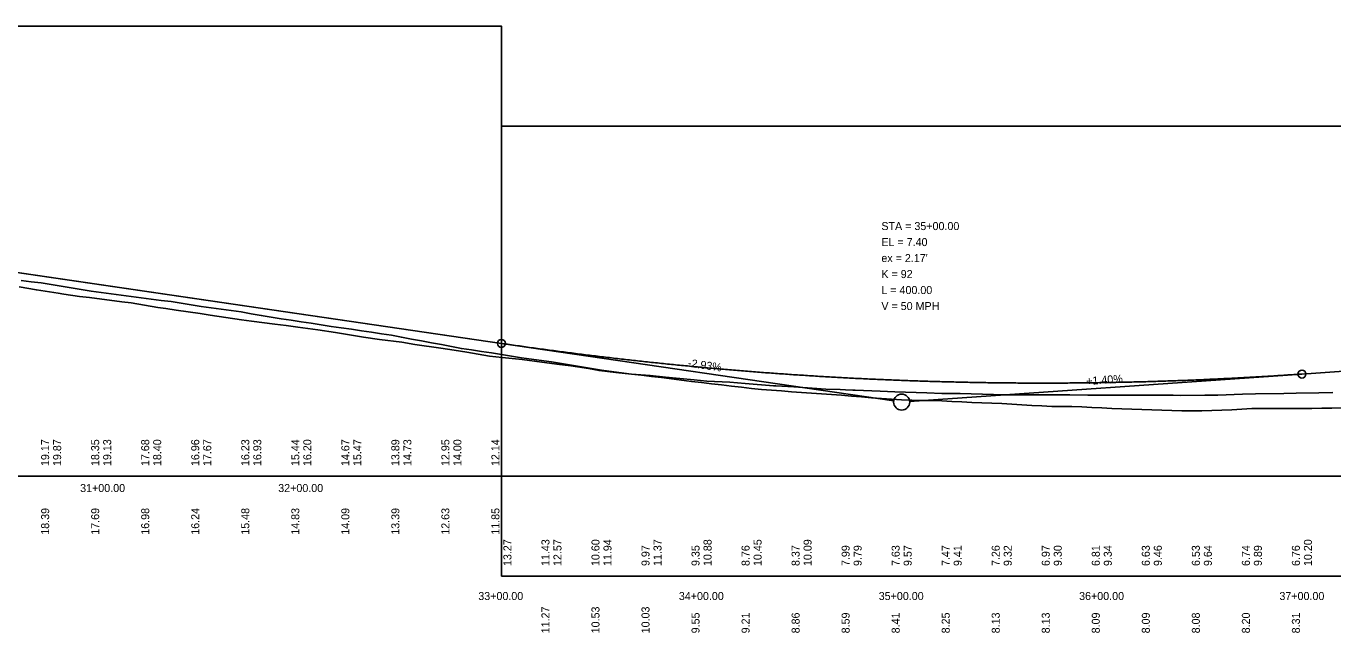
# Model space of a CAD drawing. Extents: x 3880794 to 3915434, y 287517 to 300173.
# Drawn here: x 3883601 to 3884254, y 297646 to 297949 of the extents above; entities that cross this region are included whole.
import ezdxf

# ---------------------------------------------------------------- set-up
doc = ezdxf.new("R2010")
doc.units = 0
for name, color, linetype in [('Level 1', 7, 'Continuous'), ('Level 2', 7, 'Continuous'), ('Level 30', 7, 'Continuous'), ('Level 31', 7, 'Continuous'), ('Level 32', 7, 'Continuous'), ('Level 62', 7, 'Continuous'), ('Level 63', 7, 'Continuous')]:
    doc.layers.add(name, color=color, linetype=linetype)

msp = doc.modelspace()

# ---------------------------------------------------------------- linework, layer by layer
at = {"layer": 'Level 1'}
for p, q in [((3883588.3, 297827.19), (3883838.3, 297790.52)), ((3884238.3, 297775.21), (3884538.3, 297796.23)), ((3883838.3, 297790.52), (3884034.34, 297761.77)), ((3884238.3, 297775.21), (3884042.29, 297761.47))]:
    msp.add_line(p, q, dxfattribs=at)
for points in [[(3883597.27, 297818.81), (3883605.94, 297817.28), (3883608.11, 297816.93), (3883616.77, 297815.59), (3883619.58, 297815.2), (3883627.5, 297814.06), (3883632.4, 297813.44), (3883648.68, 297811.25), (3883653.27, 297810.78), (3883666.53, 297808.52), (3883670.58, 297807.97), (3883675.8, 297807.19), (3883687.69, 297805.5), (3883692.79, 297804.56), (3883708.37, 297802.27), (3883713.41, 297801.58), (3883725, 297800.11), (3883730.7, 297799.51), (3883736.6, 297798.6), (3883746.62, 297797.24), (3883755.31, 297795.95), (3883769.41, 297793.64), (3883777.4, 297792.55), (3883788.55, 297791.08), (3883795.02, 297789.98), (3883808.04, 297788.14), (3883814.74, 297787.15), (3883821.01, 297786.18), (3883832.36, 297784.19), (3883838.61, 297783.4), (3883848.7, 297782.42), (3883858.55, 297781.16), (3883867.33, 297780.02)], [(3883867.33, 297780.02), (3883872.99, 297779.35), (3883881.77, 297777.94), (3883887.06, 297776.97), (3883895.54, 297776.01), (3883903.3, 297775.16), (3883912.6, 297774.39), (3883920.25, 297773.64), (3883934.56, 297772.27), (3883940.92, 297771.69), (3883952.45, 297771.11), (3883960.07, 297770.53), (3883974.32, 297769.31), (3883975.36, 297769.25), (3883984.42, 297768.74), (3884000.42, 297767.69), (3884007.61, 297767.44), (3884010.28, 297767.27), (3884013.95, 297767.13), (3884015.09, 297767.09), (3884027.62, 297766.65), (3884034.83, 297766.36), (3884050.85, 297765.81), (3884058.38, 297765.5), (3884059.22, 297765.48), (3884067.5, 297765.39), (3884084.25, 297764.94), (3884088.11, 297764.84), (3884095.69, 297764.82), (3884105.7, 297764.82), (3884115.48, 297764.82), (3884122.37, 297764.74), (3884131.29, 297764.68), (3884136.3, 297764.65), (3884146.02, 297764.64), (3884152.71, 297764.62), (3884164.32, 297764.63), (3884173.94, 297764.62), (3884177.81, 297764.54), (3884189.81, 297764.62), (3884196.23, 297764.68), (3884208.54, 297765.08), (3884215.17, 297765.22), (3884229.31, 297765.53), (3884235.38, 297765.69), (3884246.77, 297765.83), (3884253.82, 297765.93)]]:
    msp.add_lwpolyline(points, dxfattribs=at)
msp.add_circle((3884038.3, 297761.19), 4, dxfattribs=at)
msp.add_spline([(3883838.3, 297790.52), (3883846.3, 297789.37), (3883854.3, 297788.25), (3883862.3, 297787.16), (3883870.3, 297786.11), (3883878.3, 297785.09), (3883886.3, 297784.11), (3883894.3, 297783.16), (3883902.3, 297782.25), (3883910.3, 297781.37), (3883918.3, 297780.52), (3883926.3, 297779.72), (3883934.3, 297778.94), (3883942.3, 297778.2), (3883950.3, 297777.5), (3883958.3, 297776.83), (3883966.3, 297776.19), (3883974.3, 297775.59), (3883982.3, 297775.02), (3883990.3, 297774.49), (3883998.3, 297773.99), (3884006.3, 297773.53), (3884014.3, 297773.1), (3884022.3, 297772.71), (3884030.3, 297772.35), (3884038.3, 297772.03), (3884046.3, 297771.74), (3884054.3, 297771.48), (3884062.3, 297771.27), (3884070.3, 297771.08), (3884078.3, 297770.93), (3884086.3, 297770.81), (3884094.3, 297770.73), (3884102.3, 297770.69), (3884110.3, 297770.67), (3884118.3, 297770.7), (3884126.3, 297770.76), (3884134.3, 297770.85), (3884142.3, 297770.98), (3884150.3, 297771.14), (3884158.3, 297771.33), (3884166.3, 297771.57), (3884174.3, 297771.83), (3884182.3, 297772.13), (3884190.3, 297772.47), (3884198.3, 297772.84), (3884206.3, 297773.24), (3884214.3, 297773.68), (3884222.3, 297774.15), (3884230.3, 297774.66), (3884238.3, 297775.21)], degree=3, dxfattribs=at)
at = {"layer": 'Level 2'}
for p, q in [((3883538.3, 297834.52), (3883838.3, 297790.52)), ((3884238.3, 297775.21), (3884588.3, 297799.73)), ((3883838.3, 297790.52), (3884034.34, 297761.77)), ((3884238.3, 297775.21), (3884042.29, 297761.47))]:
    msp.add_line(p, q, dxfattribs=at)
for points in [[(3883598.3, 297821.92), (3883603.3, 297821.36), (3883608.3, 297820.8), (3883613.3, 297820.03), (3883618.3, 297819.13), (3883623.3, 297818.23), (3883628.3, 297817.43), (3883633.3, 297816.69), (3883638.3, 297815.95), (3883643.3, 297815.23), (3883648.3, 297814.57), (3883653.3, 297813.92), (3883658.3, 297813.26), (3883663.3, 297812.61), (3883668.3, 297812.01), (3883673.3, 297811.4), (3883678.3, 297810.64), (3883683.3, 297809.82), (3883688.3, 297809.01), (3883693.3, 297808.29), (3883698.3, 297807.61), (3883703.3, 297806.93), (3883708.3, 297806.24), (3883713.3, 297805.36), (3883718.3, 297804.49), (3883723.3, 297803.59), (3883728.3, 297802.86), (3883733.3, 297802.12), (3883738.3, 297801.38), (3883743.3, 297800.59), (3883748.3, 297799.8), (3883753.3, 297799.03), (3883758.3, 297798.29), (3883763.3, 297797.57), (3883768.3, 297796.84), (3883773.3, 297796.09), (3883778.3, 297795.34), (3883783.3, 297794.56), (3883788.3, 297793.63), (3883793.3, 297792.71), (3883798.3, 297791.81), (3883803.3, 297790.86), (3883808.3, 297789.9), (3883813.3, 297788.94), (3883818.3, 297787.97), (3883823.3, 297787.24), (3883828.3, 297786.52), (3883833.3, 297785.76), (3883838.3, 297784.89), (3883843.3, 297784.08), (3883848.3, 297783.26), (3883853.3, 297782.57), (3883858.3, 297781.95), (3883863.3, 297781.34), (3883868.3, 297780.51), (3883873.3, 297779.63), (3883878.3, 297778.75), (3883883.3, 297777.96), (3883888.3, 297777.17), (3883893.3, 297776.39), (3883898.3, 297775.78), (3883903.3, 297775.2), (3883908.3, 297774.61), (3883913.3, 297774.03), (3883918.3, 297773.42), (3883923.3, 297772.81), (3883928.3, 297772.19), (3883933.3, 297771.55), (3883938.3, 297770.95), (3883943.3, 297770.34), (3883948.3, 297769.74), (3883953.3, 297769.16), (3883958.3, 297768.58), (3883963.3, 297768), (3883968.3, 297767.42), (3883973.3, 297767.07), (3883978.3, 297766.72), (3883983.3, 297766.37), (3883988.3, 297766.03), (3883993.3, 297765.67), (3883998.3, 297765.3), (3884003.3, 297764.93), (3884008.3, 297764.57), (3884013.3, 297764.15), (3884018.3, 297763.72), (3884023.3, 297763.3), (3884028.3, 297762.97), (3884033.3, 297762.66), (3884038.3, 297762.35)], [(3884038.3, 297762.35), (3884043.3, 297762.07), (3884048.3, 297761.98), (3884053.3, 297761.89), (3884058.3, 297761.8), (3884063.3, 297761.54), (3884068.3, 297761.29), (3884073.3, 297761.04), (3884078.3, 297760.78), (3884083.3, 297760.63), (3884088.3, 297760.48), (3884093.3, 297760.18), (3884098.3, 297759.81), (3884103.3, 297759.41), (3884108.3, 297759.23), (3884113.3, 297759.04), (3884118.3, 297758.95), (3884123.3, 297758.89), (3884128.3, 297758.84), (3884133.3, 297758.53), (3884138.3, 297758.22), (3884143.3, 297758.02), (3884148.3, 297757.86), (3884153.3, 297757.7), (3884158.3, 297757.52), (3884163.3, 297757.34), (3884168.3, 297757.16), (3884173.3, 297756.99), (3884178.3, 297756.85), (3884183.3, 297756.81), (3884188.3, 297756.85), (3884193.3, 297756.96), (3884198.3, 297757.07), (3884203.3, 297757.32), (3884208.3, 297757.6), (3884213.3, 297757.89), (3884218.3, 297757.95), (3884223.3, 297757.97), (3884228.3, 297758.02), (3884233.3, 297758.02), (3884238.3, 297758.02), (3884243.3, 297758.04), (3884248.3, 297758.08), (3884253.3, 297758.12), (3884258.3, 297758.22)]]:
    msp.add_lwpolyline(points, dxfattribs=at)
for centre, radius in [((3883838.3, 297790.52), 2), ((3884238.3, 297775.21), 2), ((3884038.3, 297761.19), 4)]:
    msp.add_circle(centre, radius, dxfattribs=at)
msp.add_spline([(3883838.3, 297790.52), (3883846.3, 297789.37), (3883854.3, 297788.25), (3883862.3, 297787.16), (3883870.3, 297786.11), (3883878.3, 297785.09), (3883886.3, 297784.11), (3883894.3, 297783.16), (3883902.3, 297782.25), (3883910.3, 297781.37), (3883918.3, 297780.52), (3883926.3, 297779.72), (3883934.3, 297778.94), (3883942.3, 297778.2), (3883950.3, 297777.5), (3883958.3, 297776.83), (3883966.3, 297776.19), (3883974.3, 297775.59), (3883982.3, 297775.02), (3883990.3, 297774.49), (3883998.3, 297773.99), (3884006.3, 297773.53), (3884014.3, 297773.1), (3884022.3, 297772.71), (3884030.3, 297772.35), (3884038.3, 297772.03), (3884046.3, 297771.74), (3884054.3, 297771.48), (3884062.3, 297771.27), (3884070.3, 297771.08), (3884078.3, 297770.93), (3884086.3, 297770.81), (3884094.3, 297770.73), (3884102.3, 297770.69), (3884110.3, 297770.67), (3884118.3, 297770.7), (3884126.3, 297770.76), (3884134.3, 297770.85), (3884142.3, 297770.98), (3884150.3, 297771.14), (3884158.3, 297771.33), (3884166.3, 297771.57), (3884174.3, 297771.83), (3884182.3, 297772.13), (3884190.3, 297772.47), (3884198.3, 297772.84), (3884206.3, 297773.24), (3884214.3, 297773.68), (3884222.3, 297774.15), (3884230.3, 297774.66), (3884238.3, 297775.21)], degree=3, dxfattribs=at)
at = {"layer": 'Level 31'}
for centre in [(3883838.3, 297790.52), (3884238.3, 297775.21)]:
    msp.add_circle(centre, 2, dxfattribs=at)
at = {"layer": 'Level 62'}
for points in [[(3883138.3, 297724.19), (3883838.3, 297724.19), (3883838.3, 297949.19), (3883138.3, 297949.19)], [(3883138.3, 297724.19), (3883838.3, 297724.19), (3883838.3, 297949.19), (3883138.3, 297949.19)], [(3883838.3, 297674.19), (3884538.3, 297674.19), (3884538.3, 297899.19), (3883838.3, 297899.19)], [(3883838.3, 297674.19), (3884538.3, 297674.19), (3884538.3, 297899.19), (3883838.3, 297899.19)]]:
    msp.add_lwpolyline(points, close=True, dxfattribs=at)
at = {"layer": 'Level 63'}
msp.add_line((3881538.3, 297724.19), (3896411.35, 297724.19), dxfattribs=at)

# ---------------------------------------------------------------- texts
at = {"layer": 'Level 2'}
for s, p in [('STA = 35+00.00', (3884028.16, 297847.2)), ('EL = 7.40', (3884028.16, 297839.2)), ("ex = 2.17'", (3884028.16, 297831.2)), ('K = 92', (3884028.16, 297823.2)), ('L = 400.00', (3884028.16, 297815.2)), ('L = 400.00', (3884028.16, 297815.2)), ('V = 50 MPH', (3884028.16, 297807.2))]:
    msp.add_text(s, height=4, dxfattribs=at).set_placement(p)
for s, rotation, p in [('-2.93%', 351.65611, (3883931.29, 297778.91)), ('+1.40%', 4.00856, (3884130.66, 297769.67))]:
    msp.add_text(s, height=4, rotation=rotation, dxfattribs=at).set_placement(p)
at = {"layer": 'Level 30'}
for s, p in [('31+00.00', (3883627.78, 297716.19)), ('31+00.00', (3883627.78, 297716.19)), ('32+00.00', (3883726.77, 297716.19)), ('32+00.00', (3883726.77, 297716.19)), ('33+00.00', (3883826.74, 297662.19)), ('33+00.00', (3883826.74, 297662.19)), ('34+00.00', (3883926.96, 297662.19)), ('34+00.00', (3883926.96, 297662.19)), ('35+00.00', (3884026.83, 297662.19)), ('35+00.00', (3884026.83, 297662.19)), ('36+00.00', (3884126.96, 297662.19)), ('36+00.00', (3884126.96, 297662.19)), ('37+00.00', (3884227.05, 297662.19)), ('37+00.00', (3884227.05, 297662.19))]:
    msp.add_text(s, height=4, dxfattribs=at).set_placement(p)
at = {"layer": 'Level 31'}
for s, p in [('STA = 35+00.00', (3884028.16, 297847.2)), ('EL = 7.40', (3884028.16, 297839.2)), ("ex = 2.17'", (3884028.16, 297831.2)), ('K = 92', (3884028.16, 297823.2)), ('L = 400.00', (3884028.16, 297815.2)), ('V = 50 MPH', (3884028.16, 297807.2))]:
    msp.add_text(s, height=4, dxfattribs=at).set_placement(p)
for s, rotation, p in [('-2.93%', 351.65611, (3883931.29, 297778.91)), ('+1.40%', 4.00856, (3884130.66, 297769.67)), ('19.87', 90, (3883618.3, 297729.19)), ('19.13', 90, (3883643.3, 297729.19)), ('18.40', 90, (3883668.3, 297729.19)), ('17.67', 90, (3883693.3, 297729.19)), ('16.93', 90, (3883718.3, 297729.19)), ('16.20', 90, (3883743.3, 297729.19)), ('15.47', 90, (3883768.3, 297729.19)), ('14.73', 90, (3883793.3, 297729.19)), ('14.00', 90, (3883818.3, 297729.19)), ('18.39', 90, (3883612.3, 297694.84)), ('17.69', 90, (3883637.3, 297694.84)), ('16.98', 90, (3883662.3, 297694.84)), ('16.24', 90, (3883687.3, 297694.84)), ('15.48', 90, (3883712.3, 297694.84)), ('14.83', 90, (3883737.3, 297694.84)), ('14.09', 90, (3883762.3, 297694.84)), ('13.39', 90, (3883787.3, 297694.84)), ('12.63', 90, (3883812.3, 297694.84)), ('11.85', 90, (3883837.3, 297694.84)), ('13.27', 90, (3883843.3, 297679.19)), ('12.57', 90, (3883868.3, 297679.19)), ('11.94', 90, (3883893.3, 297679.19)), ('11.37', 90, (3883918.3, 297679.19)), ('10.88', 90, (3883943.3, 297679.19)), ('10.45', 90, (3883968.3, 297679.19)), ('10.09', 90, (3883993.3, 297679.19)), ('10.20', 90, (3884243.3, 297679.19)), ('9.79', 90, (3884018.3, 297679.19)), ('9.57', 90, (3884043.3, 297679.19)), ('9.41', 90, (3884068.3, 297679.19)), ('9.32', 90, (3884093.3, 297679.19)), ('9.30', 90, (3884118.3, 297679.19)), ('9.34', 90, (3884143.3, 297679.19)), ('9.46', 90, (3884168.3, 297679.19)), ('9.64', 90, (3884193.3, 297679.19)), ('9.89', 90, (3884218.3, 297679.19)), ('11.27', 90, (3883862.3, 297645.53)), ('10.53', 90, (3883887.3, 297645.53)), ('10.03', 90, (3883912.3, 297645.53)), ('9.55', 90, (3883937.3, 297645.53)), ('9.21', 90, (3883962.3, 297645.53)), ('8.86', 90, (3883987.3, 297645.53)), ('8.59', 90, (3884012.3, 297645.53)), ('8.41', 90, (3884037.3, 297645.53)), ('8.25', 90, (3884062.3, 297645.53)), ('8.13', 90, (3884087.3, 297645.53)), ('8.13', 90, (3884112.3, 297645.53)), ('8.09', 90, (3884137.3, 297645.53)), ('8.09', 90, (3884162.3, 297645.53)), ('8.08', 90, (3884187.3, 297645.53)), ('8.20', 90, (3884212.3, 297645.53)), ('8.31', 90, (3884237.3, 297645.53))]:
    msp.add_text(s, height=4, rotation=rotation, dxfattribs=at).set_placement(p)
at = {"layer": 'Level 32'}
for s, p in [('19.17', (3883612.3, 297729.19)), ('19.87', (3883618.3, 297729.19)), ('18.35', (3883637.3, 297729.19)), ('19.13', (3883643.3, 297729.19)), ('17.68', (3883662.3, 297729.19)), ('18.40', (3883668.3, 297729.19)), ('16.96', (3883687.3, 297729.19)), ('17.67', (3883693.3, 297729.19)), ('16.23', (3883712.3, 297729.19)), ('16.93', (3883718.3, 297729.19)), ('15.44', (3883737.3, 297729.19)), ('16.20', (3883743.3, 297729.19)), ('14.67', (3883762.3, 297729.19)), ('15.47', (3883768.3, 297729.19)), ('13.89', (3883787.3, 297729.19)), ('14.73', (3883793.3, 297729.19)), ('12.95', (3883812.3, 297729.19)), ('14.00', (3883818.3, 297729.19)), ('12.14', (3883837.3, 297729.19)), ('13.27', (3883843.3, 297679.19)), ('11.43', (3883862.3, 297679.19)), ('12.57', (3883868.3, 297679.19)), ('10.60', (3883887.3, 297679.19)), ('11.94', (3883893.3, 297679.19)), ('11.37', (3883918.3, 297679.19)), ('10.88', (3883943.3, 297679.19)), ('10.45', (3883968.3, 297679.19)), ('10.09', (3883993.3, 297679.19)), ('10.20', (3884243.3, 297679.19)), ('9.97', (3883912.3, 297679.19)), ('9.35', (3883937.3, 297679.19)), ('8.76', (3883962.3, 297679.19)), ('8.37', (3883987.3, 297679.19)), ('7.99', (3884012.3, 297679.19)), ('9.79', (3884018.3, 297679.19)), ('7.63', (3884037.3, 297679.19)), ('9.57', (3884043.3, 297679.19)), ('7.47', (3884062.3, 297679.19)), ('9.41', (3884068.3, 297679.19)), ('7.26', (3884087.3, 297679.19)), ('9.32', (3884093.3, 297679.19)), ('6.97', (3884112.3, 297679.19)), ('9.30', (3884118.3, 297679.19)), ('6.81', (3884137.3, 297679.19)), ('9.34', (3884143.3, 297679.19)), ('6.63', (3884162.3, 297679.19)), ('9.46', (3884168.3, 297679.19)), ('6.53', (3884187.3, 297679.19)), ('9.64', (3884193.3, 297679.19)), ('6.74', (3884212.3, 297679.19)), ('9.89', (3884218.3, 297679.19)), ('6.76', (3884237.3, 297679.19))]:
    msp.add_text(s, height=4, rotation=90, dxfattribs=at).set_placement(p)

doc.saveas('drawing.dxf')
